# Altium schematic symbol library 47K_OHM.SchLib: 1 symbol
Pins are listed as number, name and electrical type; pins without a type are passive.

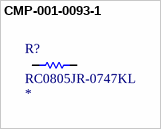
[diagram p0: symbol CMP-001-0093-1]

## CMP-001-0093-1
designator R?, comment RC0805JR-0747KL
RES SMD 47K OHM 5% 1/8W 0805; Value: 155°C; Value: 2012; Value: Tin,Lead,Matte; Value: 1.25mm; Value: Not; Value: Lead Free; Value: SMD/SMT; Value: -55°C; Value: Thick Film; Value: Unknown; Value: 47kR; Value: 100ppm/°C; Value: 2mm; Value: 125mW; Value: 150V; Value: Yageo; Value: 0805; Value: Tape and Reel; Value: 0805; Value: No
footprint Resistor 0805 47000R
pins: 1, 2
